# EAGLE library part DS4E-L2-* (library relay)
DS-RELAYS HIGHLY SENSITIVE 1500 V FCC SURGE NAiS WITHSTANDING MINIATURE RELAY Source: http://www.mew-europe.com/.. en_ds_61005_0001.pdf
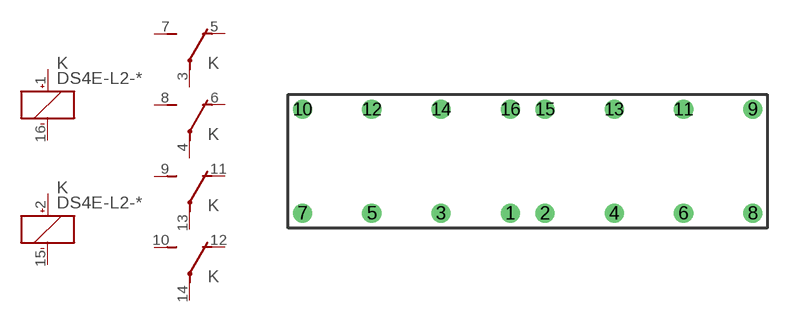
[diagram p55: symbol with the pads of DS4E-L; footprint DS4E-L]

Designator prefix K; gates S=K+- R=K+- 1=U 2=U 3=U 4=U

## DS4E-L2-1.5V (OC_FARNELL: unknown; OC_NEWARK: unknown), DS4E-L2-3V (OC_FARNELL: unknown; OC_NEWARK: unknown), DS4E-L2-5V (OC_FARNELL: unknown; OC_NEWARK: unknown), DS4E-L2-6V (OC_FARNELL: unknown; OC_NEWARK: unknown), DS4E-L2-9V (OC_FARNELL: unknown; OC_NEWARK: unknown), DS4E-L2-12V (OC_FARNELL: unknown; OC_NEWARK: unknown), DS4E-L2-24V (OC_FARNELL: unknown; OC_NEWARK: unknown), DS4E-L2-48V (OC_FARNELL: unknown; OC_NEWARK: unknown)  [DS4E-L]
1  S:+  pas
2  R:+  pas
3  1:P  pas
4  2:P  pas
5  1:O  pas
6  2:O  pas
7  1:S  pas
8  2:S  pas
9  3:S  pas
10  4:S  pas
11  3:O  pas
12  4:O  pas
13  3:P  pas
14  4:P  pas
15  R:-  pas
16  S:-  pas

## Footprint DS4E-L (pad centres in mm)
DS-RELAYS HIGHLY SENSITIVE 1500 V FCC SURGE WITHSTANDING MINIATURE RELAY Source: http://www.mew-europe.com/.. en_ds_61005_0001.pdf
drill 0.9 round: 1 -1.27,-3.81; 2 1.27,-3.81; 3 -6.35,-3.81; 4 6.35,-3.81; 5 -11.43,-3.81; 6 11.43,-3.81; 7 -16.51,-3.81; 8 16.51,-3.81; 9 16.51,3.81; 10 -16.51,3.81; 11 11.43,3.81; 12 -11.43,3.81; 13 6.35,3.81; 14 -6.35,3.81; 15 1.27,3.81; 16 -1.27,3.81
